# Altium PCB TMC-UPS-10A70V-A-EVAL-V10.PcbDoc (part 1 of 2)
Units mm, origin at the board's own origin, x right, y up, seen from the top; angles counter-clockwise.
Board outline 85 x 55 mm, 4 copper layers (Top Layer, Mid1, Mid2, Bottom Layer), stack 1.572 mm thick; 131 components, 65 nets, 443 pads, 731 vias.
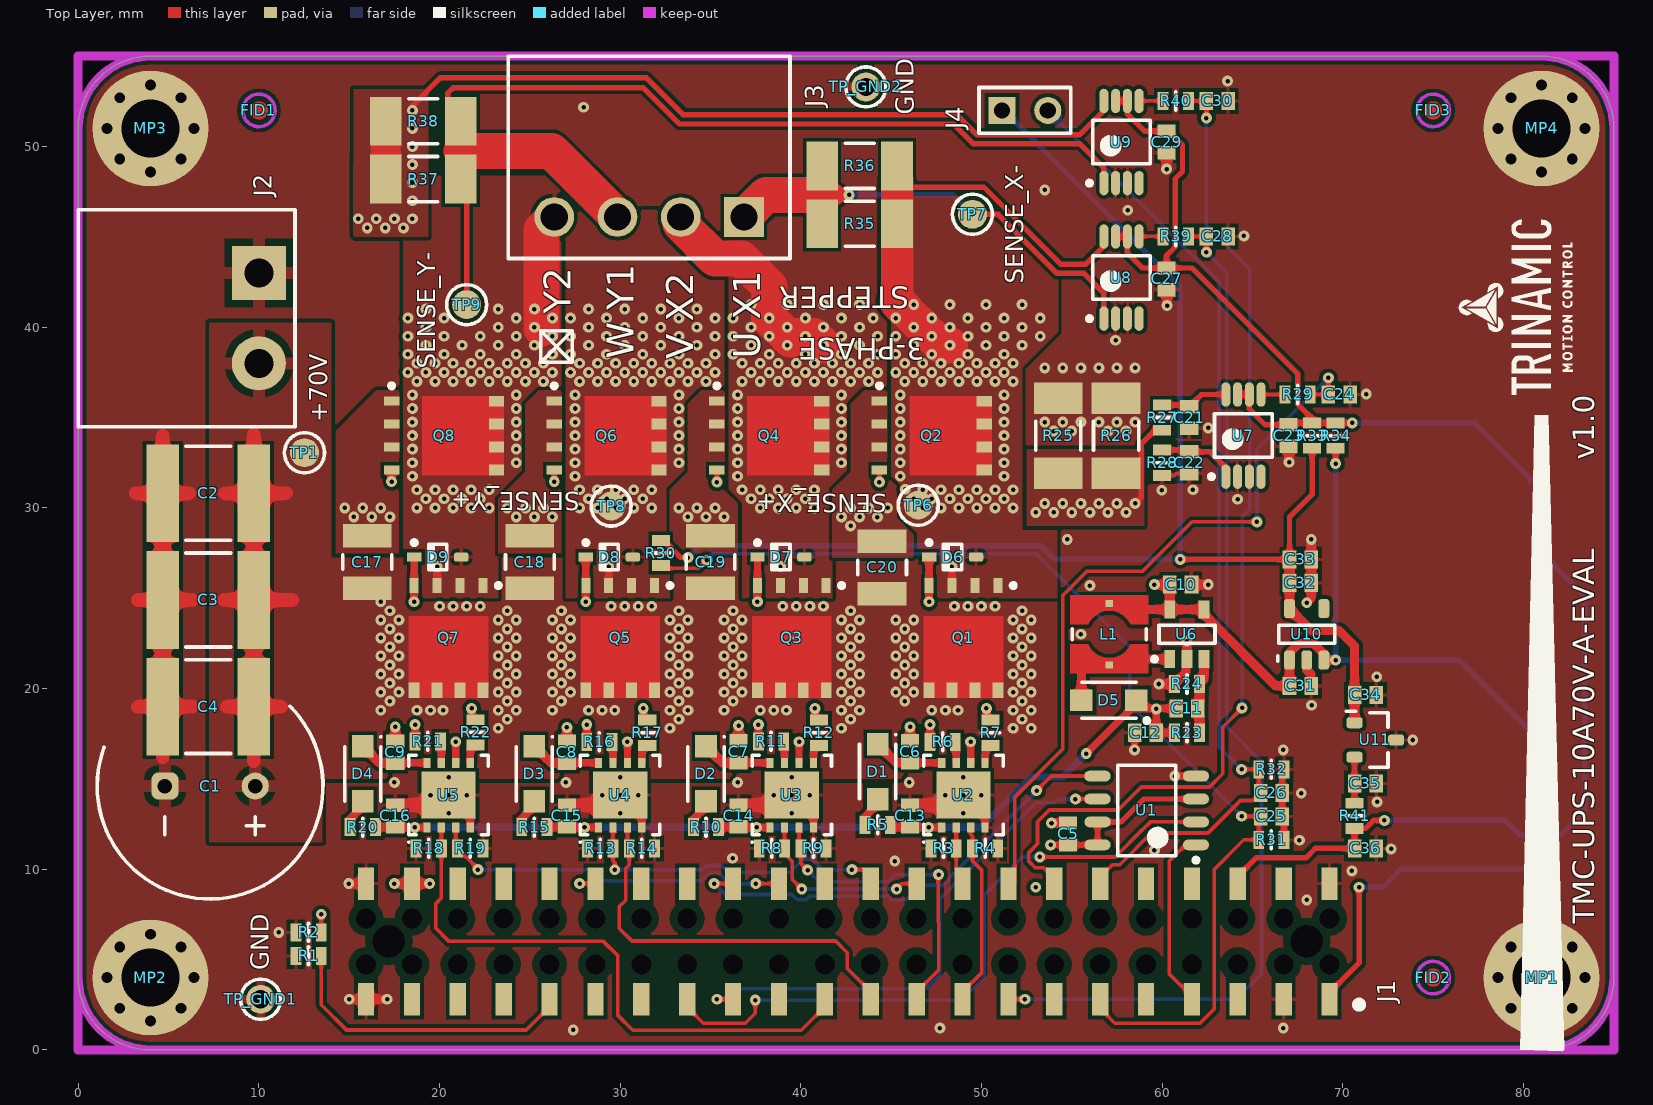
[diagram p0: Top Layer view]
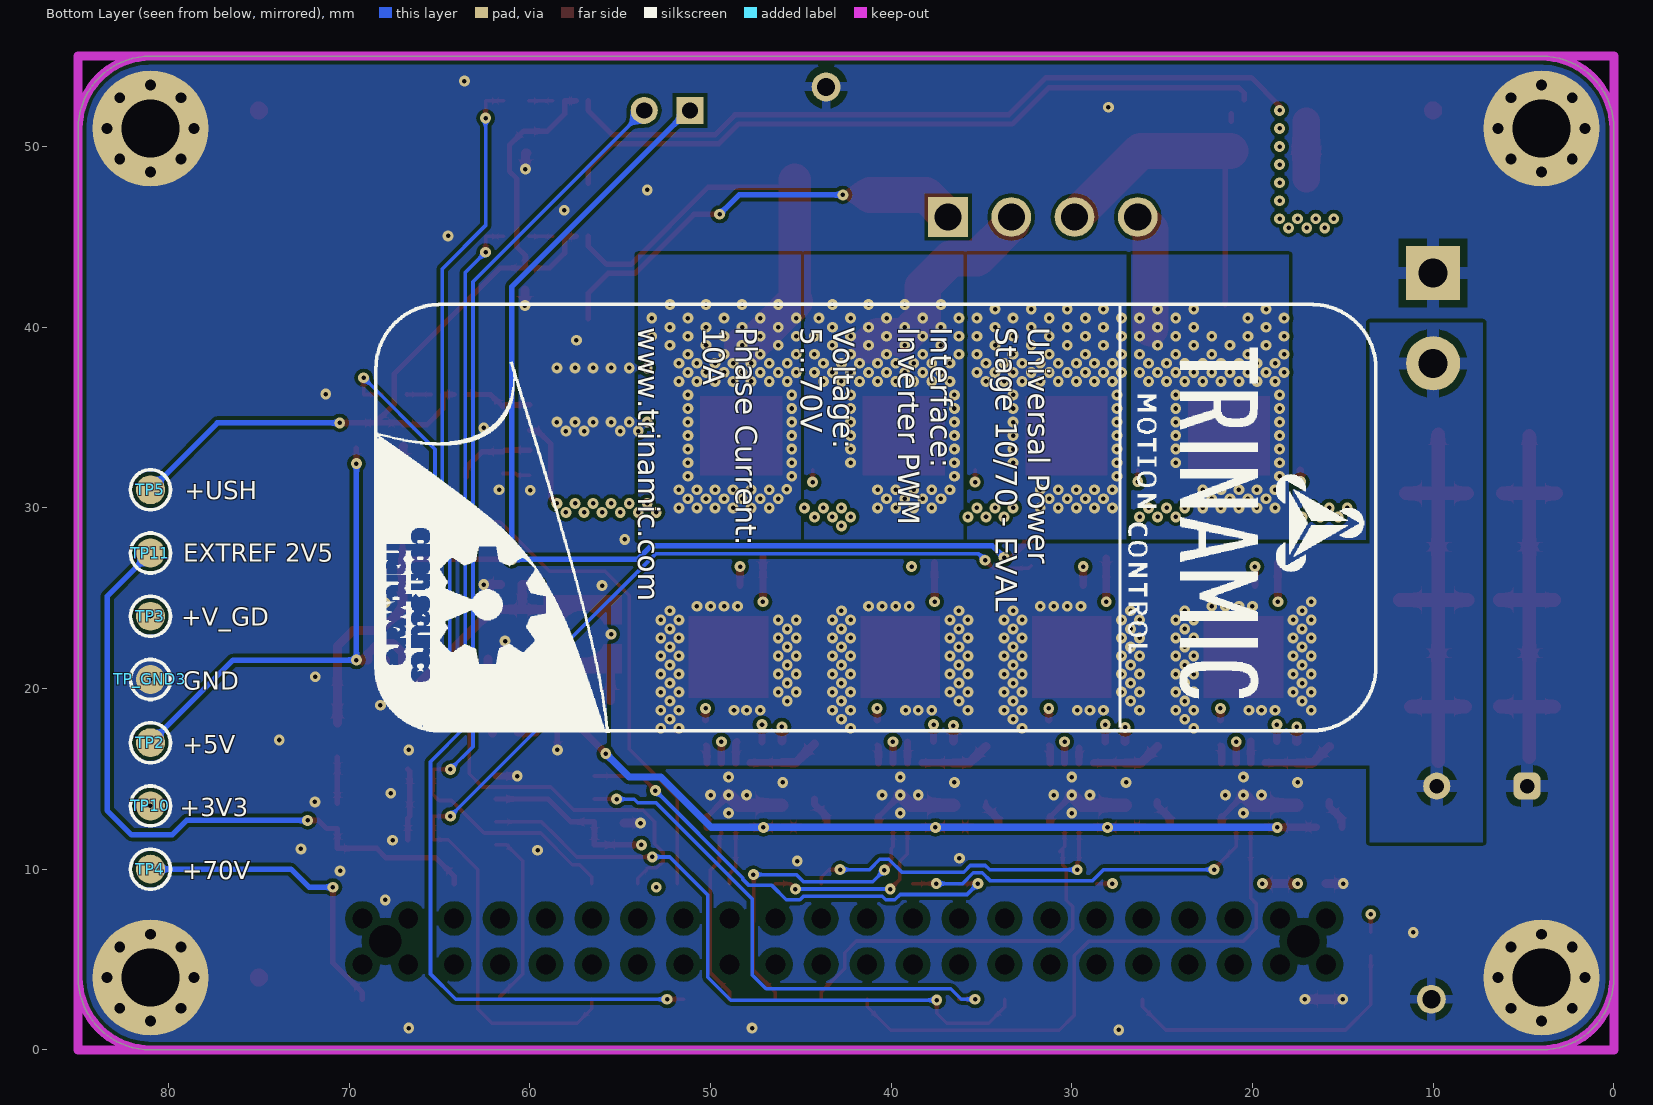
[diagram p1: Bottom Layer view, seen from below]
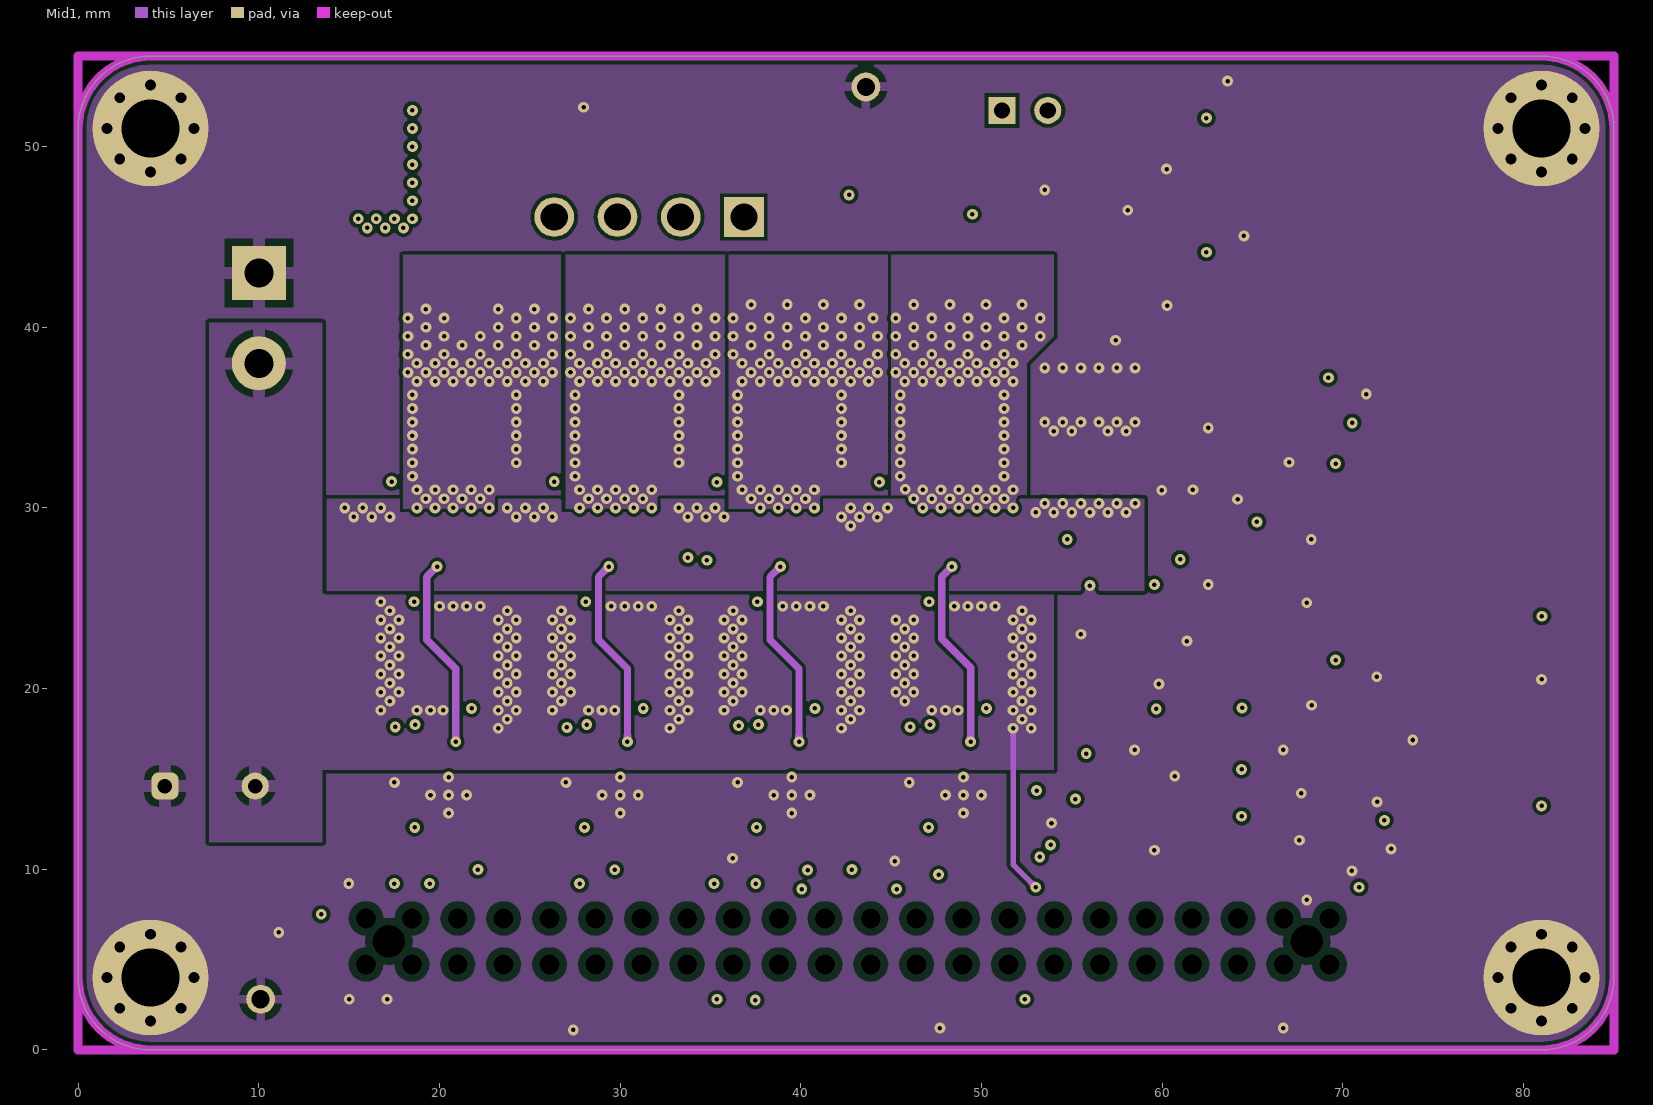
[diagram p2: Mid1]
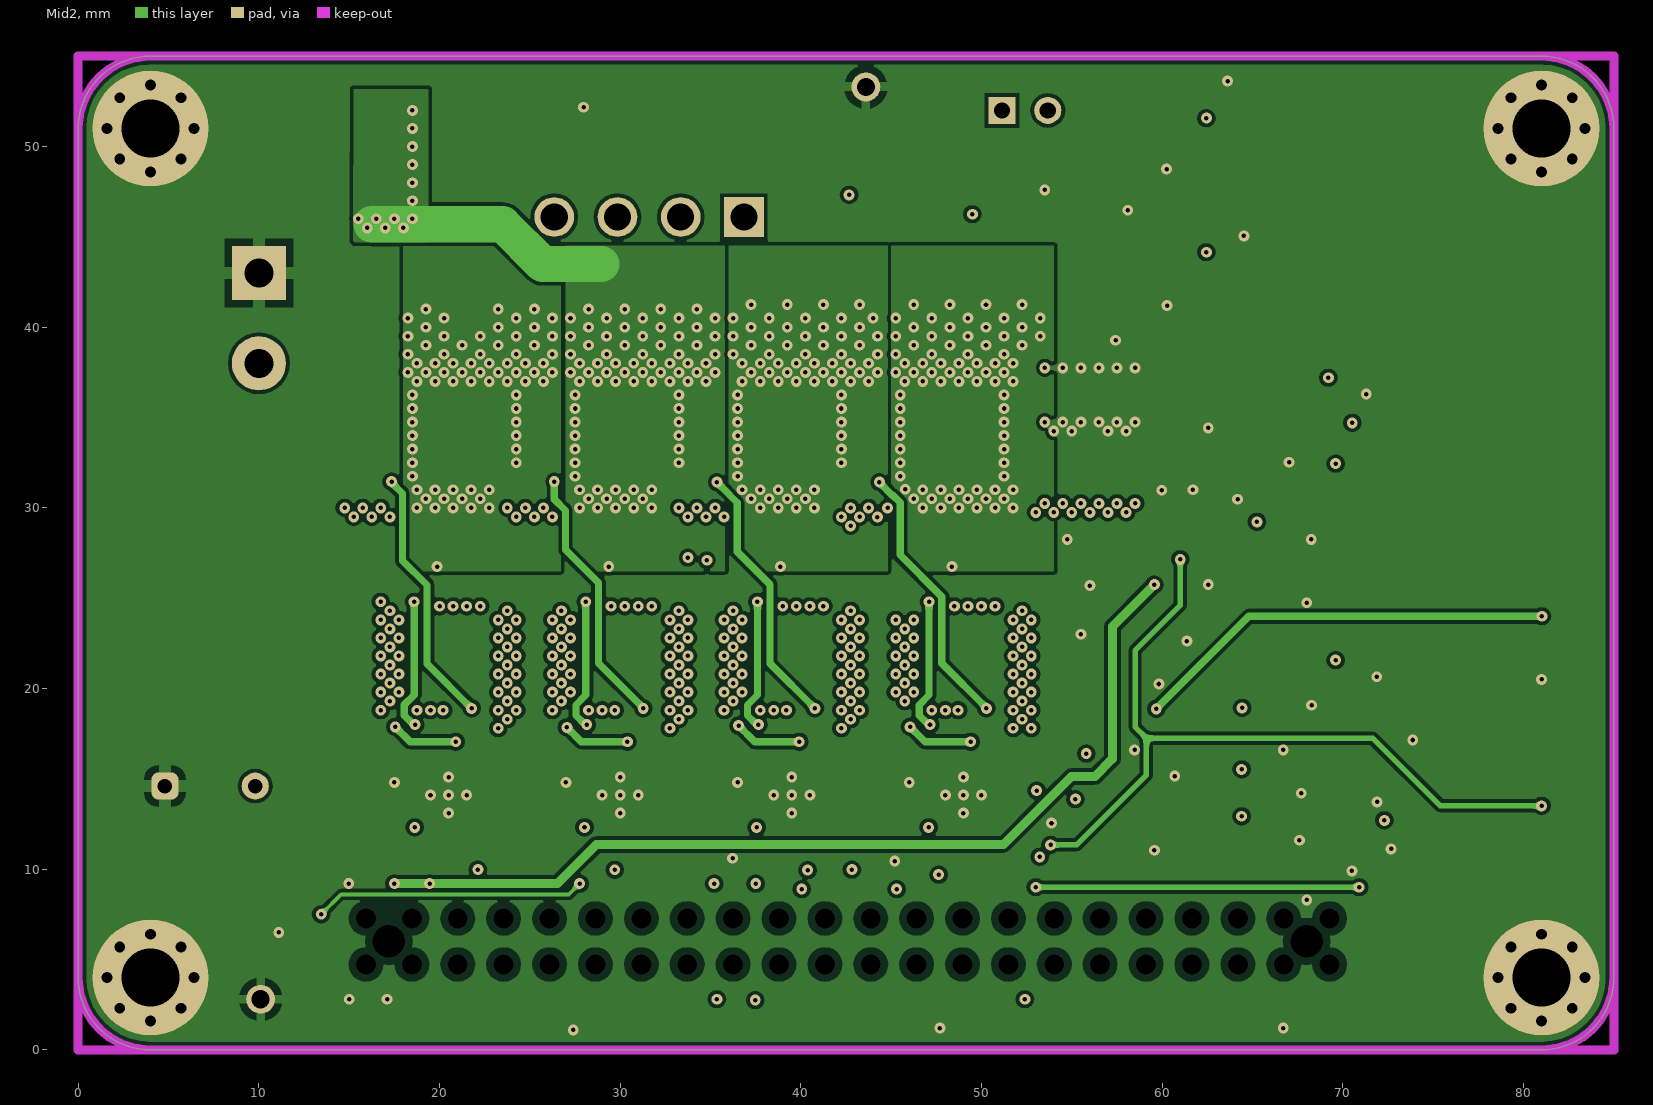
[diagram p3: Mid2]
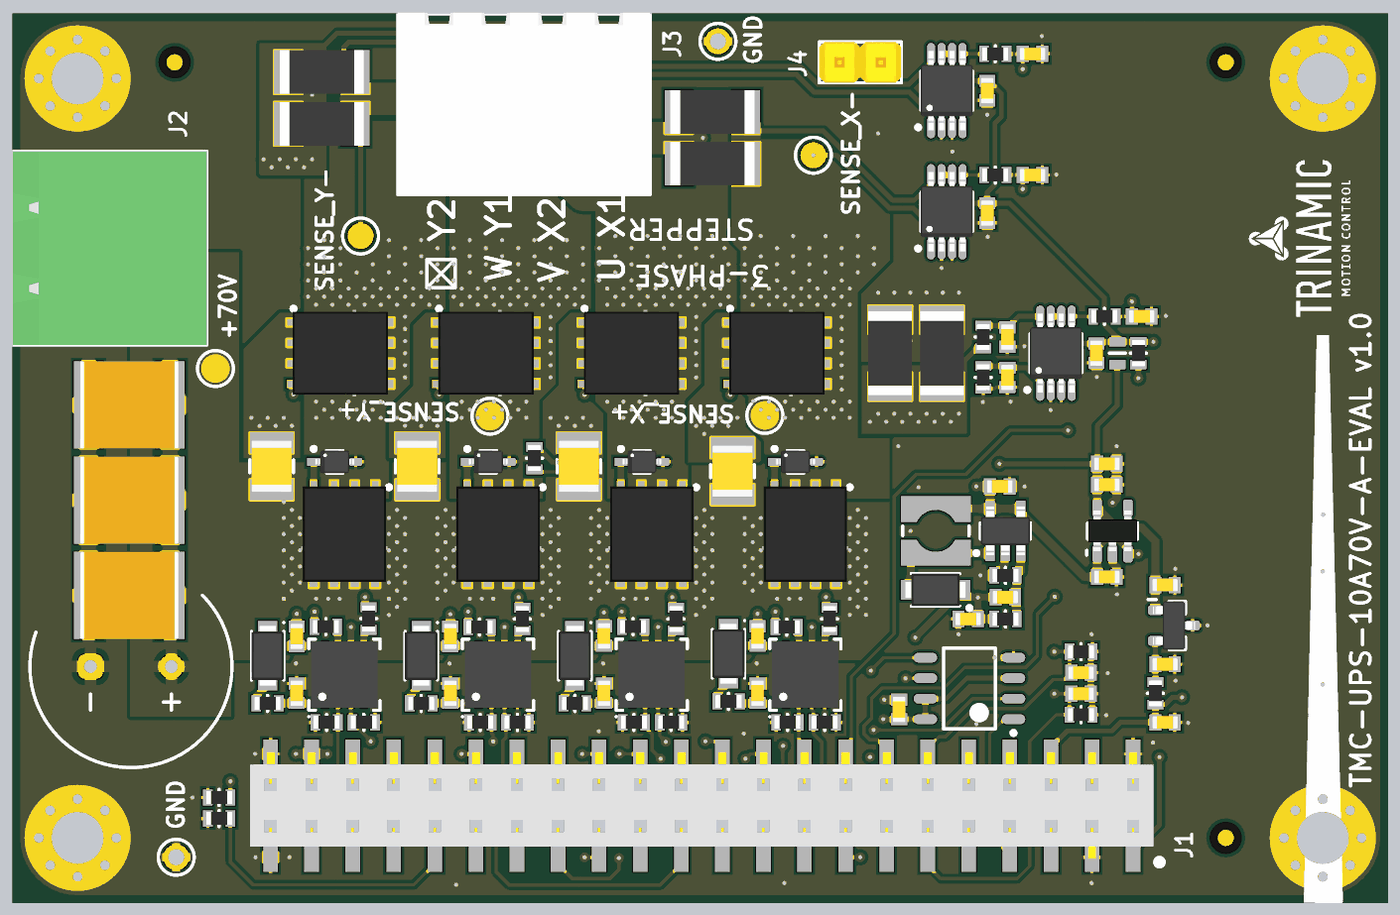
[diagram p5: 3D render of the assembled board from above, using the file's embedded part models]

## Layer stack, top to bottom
Top Soldermask: solder mask 0.0102, Solder Resist, Dk 3.5
Top Layer: signal copper 0.035
Prepreg 7628-45: prepreg 0.36, Dk 4.6
Mid1: signal copper 0.036
High Tg 1,08mm 35??m/35??m: core 0.71, FR-4, Dk 4.6
Mid2: signal copper 0.036
Prepreg 7628-45: prepreg 0.36, Dk 4.6
Bottom Layer: signal copper 0.035
Bottom Soldermask: solder mask 0.0102, Solder Resist, Dk 3.5

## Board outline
4,0 cw(c4,4) 0,4 0,51 cw(c4,51) 4,55 81,55 cw(c81,51) 85,51 85,4 cw(c81,4) 81,0

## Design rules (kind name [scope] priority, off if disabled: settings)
Clearance Clearance-unplated [IsPad and not PadIsPlated vs IsElectrical] p1: gap=0.4 ignorepadtopadclearanceinfootprint=FALSE
Clearance Clearance- [All] p2: gap=0.2 ignorepadtopadclearanceinfootprint=FALSE except(0: Arc-Hole Track-Hole SMDPad-Hole THPad-Hole Via-Hole Fill-Hole Poly-Hole Region-Hole Text-Hole; 0.125: SMDPad-SMDPad; 0.15: Track-SMDPad)
ComponentClearance [All] p1: gap=0 collisioncheckmode=3 verticalgap=0 showdistances=TRUE
DiffPairsRouting [All] p1: maxlimit=0.25 minlimit=0.25 mostfreqgap=0.25 toplayer_minwidth=0.381 toplayer_maxwidth=0.381 toplayer_prefwidth=0.381 midlayer1_minwidth=0.381 midlayer1_maxwidth=0.381 midlayer1_prefwidth=0.381 midlayer2_minwidth=0.381 midlayer2_maxwidth=0.381 midlayer2_prefwidth=0.381 bottomlayer_minwidth=0.381 bottomlayer_maxwidth=0.381 bottomlayer_prefwidth=0.381 maxuncoupledlength=12.5
FabricationTestpoint [All] p1: side=3 testpointundercomponent=TRUE minsize=0.5 maxsize=2.54 preferedsize=1.524 minholesize=0 maxholesize=1.016 preferedholesize=0.813 testpointgrid=0.025 allowsidetop=TRUE allowsidebottom=TRUE usegrid=FALSE gridtolerance=0
Height [All] p1: minheight=0 maxheight=40 prefheight=12.5
HoleSize HoleSize-PTH [All] p1: absolutevalues=TRUE maxlimit=6 minlimit=0.2 maxpercent=80.000 minpercent=20.000
HoleToHoleClearance [All] p1: gap=0.15 allowstackedmicrovias=TRUE
MinimumAnnularRing "Minimum IAR  >0.45mm" [((ObjectKind = 'Pad') OR (ObjectKind = 'Via')) And (Layer = 'MultiLayer') And (HoleDiameter > AsMM(0.45))] p1: minimumring=0.15 // minimum inner annular ring for pads > 0.45mm finished hole size
MinimumAnnularRing "Minimum IAR <=0.45mm" [((ObjectKind = 'Pad') OR (ObjectKind = 'Via')) And (Layer = 'MultiLayer') And (HoleDiameter <= AsMM(0.45))] p2: minimumring=0.15 // minimum inner annular ring for pads <= 0.45mm finished hole size
MinimumSolderMaskSliver [All] p1: minsoldermaskwidth=0.1
PlaneClearance PlaneClearance-IPI [All] p1: clearance=0.4
PlaneConnect [All] p1: planeconnectstyle=Relief reliefexpansion=0.4 reliefentries=4 reliefconductorwidth=0.2 reliefairgap=0.2
PolygonConnect PolygonConnect-Shunt [HasFootprint('RESC5025X07N')] p1: connectstyle=Direct reliefconductorwidth=0.254 reliefentries=4 polygonreliefangle="90 Angle" airgapwidth=0.254
PolygonConnect PolygonConnect-MT [HasFootprint('MTG3,2_6,4-VIA')] p2: connectstyle=Direct reliefconductorwidth=0.254 reliefentries=4 polygonreliefangle="90 Angle" airgapwidth=0.254
PolygonConnect PolygonConnect-JP2 [HasFootprint('691313710002')] p3: connectstyle=Relief reliefconductorwidth=0.7 reliefentries=4 polygonreliefangle="90 Angle" airgapwidth=0.4
PolygonConnect PolygonConnect-J1 [HasFootprint('AKL320-02')] p4: connectstyle=Relief reliefconductorwidth=0.7 reliefentries=4 polygonreliefangle="90 Angle" airgapwidth=0.4
PolygonConnect PolygonConnect-CAP [HasFootprint('CAPAE12_5X20')] p5: connectstyle=Relief reliefconductorwidth=0.7 reliefentries=4 polygonreliefangle="90 Angle" airgapwidth=0.4
PolygonConnect PolygonConnect-TP [HasFootprint('TP100P254')] p6: connectstyle=Direct reliefconductorwidth=0.254 reliefentries=4 polygonreliefangle="90 Angle" airgapwidth=0.254
PolygonConnect PolygonConnect-TP_1 [HasFootprint('TP100P254-TH')] p7: connectstyle=Relief reliefconductorwidth=0.5 reliefentries=4 polygonreliefangle="90 Angle" airgapwidth=0.4
PolygonConnect PolygonConnect-MOSFET [HasFootprint('PG-TDSON-8')] p8: connectstyle=Direct reliefconductorwidth=0.254 reliefentries=4 polygonreliefangle="90 Angle" airgapwidth=0.254
PolygonConnect PolygonConnect-CAPC3225N [HasFootprint('CAPC3225N')] p9: connectstyle=Direct reliefconductorwidth=0.254 reliefentries=4 polygonreliefangle="90 Angle" airgapwidth=0.254
PolygonConnect PolygonConnect-Via [IsVia] p10: connectstyle=Direct reliefconductorwidth=0.2 reliefentries=4 polygonreliefangle="90 Angle" airgapwidth=0.254
PolygonConnect PolygonConnect-xTW [All] p11: connectstyle=Relief reliefconductorwidth=0.2 reliefentries=4 polygonreliefangle="90 Angle" airgapwidth=0.2
RoutingCorners [All] p1: cornerstyle=45-Degree minsetback=2.5 maxsetback=2.5
RoutingVias "RoutingVias <= 0.45mm" [All] p1: holewidth=0.25 width=0.6 viastyle="Through Hole" minholewidth=0.2 minwidth=0.5 maxholewidth=0.6 maxwidth=1
SilkToSilkClearance [All] p1: silktosilkclearance=0.2
SilkToSolderMaskClearance SilkscreenOverComponentPads [IsPad] p1: minsilkscreentomaskgap=0.2 clearancetoexposedcopper=TRUE
SolderMaskExpansion SolderMaskExpansionVia [IsVia] p1: expansion=0.1 soldermaskfromhole=TRUE
SolderMaskExpansion [All] p2: expansion=0.08
Width Width-xTW [All] p1: maxlimit=2 minlimit=0.15 preferedwidth=0.2 midlayer1_minwidth=0.2 midlayer2_minwidth=0.2 bottomlayer_minwidth=0.2 minimp=50.000000 maximp=50.000000 favimp=50.000000
18 further rules are at their usual default settings.

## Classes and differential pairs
component class TMC-UPS-10A70V-A-EVAL-V10_Power_Sense: C27 C28 C29 C30 C31 C32 C33 C34 C35 C36 R35 R36 R37 R38 R39 R40 R41 TP6 TP7 TP8 TP9 TP10 TP11 U8 U9 U10 U11
component class TMC-UPS-10A70V-A-EVAL-V10_MOSFETs: C17 C18 C19 C20 C21 C22 C23 C24 C25 C26 D6 D7 D8 D9 J4 Q1 Q2 Q3 Q4 Q5 Q6 Q7 Q8 R25 R26 R27 R28 R29 R30 R31 R32 R33 R34 TP4 TP5 U7
component class TMC-UPS-10A70V-A-EVAL-V10_Predriver: C6 C7 C8 C9 C10 C11 C12 C13 C14 C15 C16 D1 D2 D3 D4 D5 L1 R3 R4 R5 R6 R7 R8 R9 R10 R11 R12 R13 R14 R15 R16 R17 R18 R19 R20 R21 R22 R23 R24 TP2 TP3 U2 U3 U4 U5 U6
component class TMC-UPS-10A70V-A-EVAL-V10_Main: C1 C2 C3 C4 C5 J1 J2 J3 MP1 MP2 MP3 MP4 R1 R2 TP1 TP_GND1 TP_GND2 TP_GND3 U1

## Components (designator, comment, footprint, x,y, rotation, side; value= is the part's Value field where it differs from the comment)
C1 "CAPP2" CAPAE12_5X20 7.3,14.6 r0 top
C2 "CAPC" CAPC5750X28N 7.2,30.8 r0 top value=10u
C3 "CAPC" CAPC5750X28N 7.2,24.9 r0 top value=10u
C4 "CAPC" CAPC5750X28N 7.2,19 r0 top value=10u
C5 "CAPC" CAPC1608N 54.8,11.95 r270 top value=100n
C6 "" CAPC1608N 46.05,16.5 r90 top value=100n
C7 "" CAPC1608N 36.55,16.5 r90 top value=100n
C8 "" CAPC1608N 27.05,16.475 r90 top value=100n
C9 "" CAPC1608N 17.55,16.475 r90 top value=100n
C10 "CAPC" CAPC1608N 61.025,25.75 r180 top value=10u
C11 "CAPC" CAPC1608N 61.375,18.9 r180 top value=25p
C12 "CAPC" CAPC1608N 59.075,17.55 r0 top value=4.7u
C13 "CAPC" CAPC1608N 46.05,12.95 r270 top value=1u
C14 "CAPC" CAPC1608N 36.55,12.95 r270 top value=1u
C15 "CAPC" CAPC1608N 27.05,12.95 r270 top value=1u
C16 "CAPC" CAPC1608N 17.55,12.95 r270 top value=1u
C17 "CAPC" CAPC3225N 16,27 r270 top value=4.7u
C18 "CAPC" CAPC3225N 25,27 r270 top value=4.7u
C19 "CAPC" CAPC3225N 35,27 r270 top value=4.7u
C20 "CAPC" CAPC3225N 44.5,26.7 r270 top value=4.7u
C21 "CAPC" CAPC1608N 61.5,35 r90 top value=100p
C22 "CAPC" CAPC1608N 61.5,32.5 r90 top value=100p
C23 "CAPC" CAPC1608N 67,34 r90 top value=100n
C24 "" CAPC1608N 69.8,36.275 r180 top value=2.2n
C25 "CAPC" CAPC1608N 66.05,12.925 r180 top value=100n
C26 "CAPC" CAPC1608N 66.05,14.225 r180 top value=100n
C27 "CAPC" CAPC1608N 60.25,42.675 r270 top value=100n
C28 "" CAPC1608N 63.05,45.025 r180 top value=2.2n
C29 "CAPC" CAPC1608N 60.25,50.25 r90 top value=100n
C30 "" CAPC1608N 63.05,52.525 r180 top value=2.2n
C31 "CAPC" CAPC1608N 67.65,20.15 r180 top value=100n
C32 "CAPC" CAPC1608N 67.65,25.85 r180 top value=4.7u
C33 "CAPC" CAPC1608N 67.65,27.15 r180 top value=100n
C34 "CAPC" CAPC1608N 71.25,19.65 r180 top value=100n
C35 "CAPC" CAPC1608N 71.25,14.75 r180 top value=100n
C36 "CAPC" CAPC1608N 71.25,11.15 r180 top value=100n
D1 "DIO-SCHOTTKY" SODFL370X140-2N 44.25,15.4 r270 top value="1A, 100V"
D2 "DIO-SCHOTTKY" SODFL370X140-2N 34.75,15.275 r270 top value="1A, 100V"
D3 "DIO-SCHOTTKY" SODFL370X140-2N 25.25,15.275 r270 top value="1A, 100V"
D4 "DIO-SCHOTTKY" SODFL370X140-2N 15.75,15.275 r270 top value="1A, 100V"
D5 "DIO-SCHOTTKY" SODFL370X140-2N 57.05,19.35 r180 top value="1A, 100V"
D6 "ZENER" SOD2512X100N 48.4,27.275 r0 top value="13V, 0.3W"
D7 "ZENER" SOD2512X100N 38.9,27.275 r0 top value="13V, 0.3W"
D8 "ZENER" SOD2512X100N 29.4,27.275 r0 top value="13V, 0.3W"
D9 "ZENER" SOD2512X100N 19.9,27.275 r0 top value="13V, 0.3W"
FID1 "Comment" FID10X20 10,52 r90 top
FID2 "Comment" FID10X20 75,4 r90 top
FID3 "Comment" FID10X20 75,52 r90 top
J1 "PTC" HLE-122-02-F-DV 42.6,6 r180 top locked value=44pin
J2 "HDR1x2A" AKL320-02 10,40.5 r90 top locked value="2 pin"
J3 "HDR1x4A" PT11304HBBN 31.6,46.1 r0 top locked value="4 pin, 3.5mm"
J4 "HDR1x2" HDRP1X2_2_54 52.4,52 r0 top locked value="2 pin"
L1 "INDM" 744031100 57.075,23 r270 top value=10u
MP1 "MTG" MTG3,2_6,4-VIA 81,4 r90 top value="3.2x6.4 VIA"
MP2 "MTG" MTG3,2_6,4-VIA 4,4 r90 top value="3.2x6.4 VIA"
MP3 "MTG" MTG3,2_6,4-VIA 4,51 r90 top value="3.2x6.4 VIA"
MP4 "MTG" MTG3,2_6,4-VIA 81,51 r90 top value="3.2x6.4 VIA"
Q1 "" PG-TDSON-8 49,22.8 r180 top value="80V 100A"
Q2 "" PG-TDSON-8 47.25,34 r270 top value="80V 100A"
Q3 "" PG-TDSON-8 39.5,22.8 r180 top value="80V 100A"
Q4 "" PG-TDSON-8 38.25,34 r270 top value="80V 100A"
Q5 "" PG-TDSON-8 30,22.8 r180 top value="80V 100A"
Q6 "" PG-TDSON-8 29.25,34 r270 top value="80V 100A"
Q7 "" PG-TDSON-8 20.5,22.8 r180 top value="80V 100A"
Q8 "" PG-TDSON-8 20.25,34 r270 top value="80V 100A"
R1 "RESC" RESC1608N 12.75,5.2 r0 top value=10k
R2 "RESC" RESC1608N 12.75,6.5 r0 top value=10k
R3 "RESC" RESC1608N 47.9,11.15 r0 top value=10k
R4 "RESC" RESC1608N 50.2,11.15 r180 top value=10k
R5 "" RESC1608N 44.25,12.45 r180 top value=2.2
R6 "" RESC1608N 47.85,17.05 r180 top value=2.2
R7 "" RESC1608N 50.5,17.55 r90 top value=2.2
R8 "RESC" RESC1608N 38.4,11.15 r0 top value=10k
R9 "RESC" RESC1608N 40.7,11.15 r180 top value=10k
R10 "" RESC1608N 34.75,12.325 r180 top value=2.2
R11 "" RESC1608N 38.35,17.075 r180 top value=2.2
R12 "" RESC1608N 41,17.55 r90 top value=2.2
R13 "RESC" RESC1608N 28.9,11.15 r0 top value=10k
R14 "RESC" RESC1608N 31.2,11.15 r180 top value=10k
R15 "" RESC1608N 25.25,12.325 r180 top value=2.2
R16 "" RESC1608N 28.85,17.05 r180 top value=2.2
R17 "" RESC1608N 31.5,17.55 r90 top value=2.2
R18 "RESC" RESC1608N 19.4,11.15 r0 top value=10k
R19 "RESC" RESC1608N 21.7,11.15 r180 top value=10k
R20 "" RESC1608N 15.75,12.325 r180 top value=2.2
R21 "" RESC1608N 19.35,17.075 r180 top value=2.2
R22 "" RESC1608N 22,17.575 r90 top value=2.2
R23 "RESC" RESC1608N 61.375,17.55 r180 top value=12k
R24 "RESC" RESC1608N 61.375,20.25 r0 top value=1.5k
R25 "RESC" RESC5025X07N 54.25,34 r270 top value=15m
R26 "RESC" RESC5025X07N 57.45,34 r270 top value=15m
R27 "RESC" RESC1608N 60,35 r90 top value=100
R28 "RESC" RESC1608N 60,32.5 r90 top value=100
R29 "RESC" RESC1608N 67.5,36.275 r0 top value=1k
R30 "RESC" RESC1608N 32.25,27.5 r90 top value="10k NTC"
R31 "RESC" RESC1608N 66.05,11.625 r180 top value=10k
R32 "RESC" RESC1608N 66.05,15.525 r180 top value=10k
R33 "RESC" RESC1608N 68.3,34 r90 top value=DNP
R34 "RESC" RESC1608N 69.6,34 r90 top value=0
R35 "RESC" RESC5025X07N 43.25,45.725 r0 top value=15m
R36 "RESC" RESC5025X07N 43.25,48.925 r0 top value=15m
R37 "RESC" RESC5025X07N 19.1,48.2 r180 top value=15m
R38 "RESC" RESC5025X07N 19.1,51.4 r180 top value=15m
R39 "RESC" RESC1608N 60.75,45.025 r0 top value=1k
R40 "RESC" RESC1608N 60.75,52.525 r0 top value=1k
R41 "RESC" RESC1608N 70.65,12.95 r270 top value=10
TP1 "+70V" TP100P254 12.525,33.05 r0 top value="c160 (P100 probe)"
TP2 "+5V" TP100P254 81,17 r180 bottom value="c160 (P100 probe)"
TP3 "+V_GD" TP100P254 81,24 r180 bottom value="c160 (P100 probe)"
TP4 "+70V" TP100P254 81,10 r180 bottom value="c160 (P100 probe)"
TP5 "+USH" TP100P254 81,31 r180 bottom value="c160 (P100 probe)"
TP6 "SENSE_X+" TP100P254 46.5,30.15 r90 top locked value="c160 (P100 probe)"
TP7 "SENSE_X-" TP100P254 49.5,46.25 r90 top locked value="c160 (P100 probe)"
TP8 "SENSE_Y+" TP100P254 29.5,30.1 r90 top locked value="c160 (P100 probe)"
TP9 "SENSE_Y-" TP100P254 21.5,41.25 r90 top value="c160 (P100 probe)"
TP10 "+3V3" TP100P254 81,13.5 r180 bottom value="c160 (P100 probe)"
TP11 "EXTREF 2V5" TP100P254 81,27.5 r180 bottom value="c160 (P100 probe)"
TP_GND1 "GND" TP100P254-TH 10.1,2.8 r180 top locked value="c160h100 (P100 TH)"
TP_GND2 "GND" TP100P254-TH 43.6,53.3 r180 top locked value="c160h100 (P100 TH)"
TP_GND3 "GND" TP100P254 81,20.5 r180 bottom value="c160 (P100 probe)"
U1 "" SOIC127P600X175-8N 59.15,13.25 r180 top value=128Kb
U2 "" PSON80P400X80_HS-9N 49,14.1 r90 top value="108V 1A"
U3 "" PSON80P400X80_HS-9N 39.5,14.1 r90 top value="108V 1A"
U4 "" PSON80P400X80_HS-9N 30,14.1 r90 top value="108V 1A"
U5 "" PSON80P400X80_HS-9N 20.5,14.1 r90 top value="108V 1A"
U6 "LMR62014" SOT95P280X145-5N 61.375,23 r90 top value=1.4A
U7 "*" TSOP65P490X95-8N 64.5,34 r90 top value=CMVR{}70V
U8 "*" TSOP65P490X95-8N 57.75,42.75 r90 top value=CMVR{}70V
U9 "*" TSOP65P490X95-8N 57.75,50.25 r90 top value=CMVR{}70V
U10 "" SOT95P270X145-5N 68,23 r90 top value="150mA 3.3V"
U11 "*" SOT95P280X130-3N 71.8,17.15 r0 top value=2.5V

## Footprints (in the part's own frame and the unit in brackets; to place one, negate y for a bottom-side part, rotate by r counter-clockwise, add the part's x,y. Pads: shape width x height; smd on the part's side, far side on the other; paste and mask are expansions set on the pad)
744031100 [mm] "Wuerth Precision Wire Wound Inductor, 2-Leads, Body 3.80x3.80mm, IPC Medium Density"
  rect 0.4x0.4 smd: 1(-1.7,0) 2(1.7,0)
  Top Layer region: 0.55,2.15 2.15,2.15 2.15,-2.15 0.55,-2.15 0.55,-1.179 0.549,-1.179 1.01,-0.819 1.267,-0.293 1.267,0.293 1.01,0.819 0.549,1.179 0.549,1.179 0.55,1.182
  Top Layer region: -0.55,-2.15 -2.15,-2.15 -2.15,2.15 -0.55,2.15 -0.55,1.179 -0.549,1.179 -1.01,0.819 -1.267,0.293 -1.267,-0.293 -1.01,-0.819 -0.549,-1.179 -0.549,-1.179 -0.55,-1.182
  silkscreen extent -0.3,-2.05 0.3,2.05, body extent -2.05,-2.05 2.05,2.05, height 1.8
AKL320-02 [mm] "Box header for AKL 349, 2-pin, RM 5.0"
  rect 3x3 hole 1.6: 1(2.5,0)
  round 3 hole 1.6: 2(-2.5,0)
  silkscreen extent -6,-2 6,10, body extent -6,-2 6,10, height 8.55
CAPAE12_5X20 [mm] "Aluminium Capacitor, Radial, H=20mm, D=12.5mm"
  rrect50% 1.5x1.5 hole 0.8: 1(-2.5,0)
  round 1.5 hole 0.8: 2(2.5,0)
  silkscreen extent -6.25,-6.25 6.25,4.42
CAPC1608N [mm] "Chip capacitor. C1608 (0603)."
  rect 0.75x1 smd: 1(-0.6,0) 2(0.6,0)
  body extent -0.8,-0.4 0.8,0.4, height 0.92
CAPC3225N [mm] "Chip capacitor. C3225 (1210)."
  rect 1.3x2.7 smd: 1(-1.45,0) 2(1.45,0)
  silkscreen extent -0.4,-1.35 0.4,1.35, body extent -1.6,-1.25 1.6,1.25, height 2.79
CAPC5750X28N [mm] "Chip Capacitor, 2-Leads, Body 5.70x5.00mm, IPC Medium Density"
  rect 1.8x5.4 smd: 1(-2.525,0) 2(2.525,0)
  silkscreen extent -1.25,-2.6 1.25,2.6, body extent -3.05,-2.7 3.05,2.7, height 2.79
FID10X20 [mm] "Fiducial"
  Top Layer circle w0.5: c0,0 r0.25
  Top Layer keep-out circle w0.2: c0,0 r0.9
HDRP1X2_2_54 [mm] "Pin Header, Single Row, 2 pos, 2.54mm"
  rect 1.5x1.5 hole 0.9: 1(-1.27,0)
  round 1.5 hole 0.9: 2(1.27,0)
  silkscreen extent -2.54,-1.27 2.54,1.27, body extent -2.54,-1.27 2.54,1.27, height 9.5
HLE-122-02-F-DV [mm] "24 Position Receptacle, Bottom Entry Connector Gold 0.100\" (2.54mm) Surface Mount"
  round 1 hole 1.1 unplated: 0(-26.67,-1.27) 0(-26.67,1.27) 0(-24.13,-1.27) 0(-24.13,1.27) 0(-21.59,-1.27) 0(-21.59,1.27) 0(-19.05,-1.27) 0(-19.05,1.27) 0(-16.51,-1.27) 0(-16.51,1.27) 0(-13.97,-1.27) 0(-13.97,1.27) 0(-11.43,-1.27) 0(-11.43,1.27) 0(-8.89,-1.27) 0(-8.89,1.27) 0(-6.35,-1.27) 0(-6.35,1.27) 0(-3.81,-1.27) 0(-3.81,1.27) 0(-1.27,1.27) 0(-1.27,-1.27) 0(1.27,1.27) 0(1.27,-1.27) 0(3.81,-1.27) 0(3.81,1.27) 0(6.35,-1.27) 0(6.35,1.27) 0(8.89,-1.27) 0(8.89,1.27) 0(11.43,-1.27) 0(11.43,1.27) 0(13.97,-1.27) 0(13.97,1.27) 0(16.51,-1.27) 0(16.51,1.27) 0(19.05,-1.27) 0(19.05,1.27) 0(21.59,-1.27) 0(21.59,1.27) 0(24.13,-1.27) 0(24.13,1.27) 0(26.67,-1.27) 0(26.67,1.27)
  round 1 hole 1.8 unplated: 0(-25.4,0) 0(25.4,0)
  rect 0.9x1.8 smd: 1(-26.67,3.2) 2(-26.67,-3.2) 3(-24.13,3.2) 4(-24.13,-3.2) 5(-21.59,3.2) 6(-21.59,-3.2) 7(-19.05,3.2) 8(-19.05,-3.2) 9(-16.51,3.2) 10(-16.51,-3.2) 11(-13.97,3.2) 12(-13.97,-3.2) 13(-11.43,3.2) 14(-11.43,-3.2) 15(-8.89,3.2) 16(-8.89,-3.2) 17(-6.35,3.2) 18(-6.35,-3.2) 19(-3.81,3.2) 20(-3.81,-3.2) 21(-1.27,3.2) 22(-1.27,-3.2) 23(1.27,3.2) 24(1.27,-3.2) 25(3.81,3.2) 26(3.81,-3.2) 27(6.35,3.2) 28(6.35,-3.2) 29(8.89,3.2) 30(8.89,-3.2) 31(11.43,3.2) 32(11.43,-3.2) 33(13.97,3.2) 34(13.97,-3.2) 35(16.51,3.2) 36(16.51,-3.2) 37(19.05,3.2) 38(19.05,-3.2) 39(21.59,3.2) 40(21.59,-3.2) 41(24.13,3.2) 42(24.13,-3.2) 43(26.67,3.2) 44(26.67,-3.2)
  silkscreen extent -28.5,3.3 -28.1,3.7, body extent -27.94,-3.29 27.94,3.29, height 3.51
MTG3,2_6,4-VIA [mm] "3,2mm ID/6.4mm OD mounting hole, reinforced with vias"
  round 6.4 hole 3.2 paste-3.3: 1(0,0)
PG-TDSON-8 [mm]
  rect 0.5x0.85 smd paste-0.05: 1(-1.905,-2.9) 2(-0.635,-2.9) 3(0.635,-2.9) 4(1.905,-2.9)
  rect 0.6x0.85 smd paste-0.05: 5(1.905,2.9) 6(0.635,2.9) 7(-0.635,2.9) 8(-1.905,2.9)
  rect 0.1x0.1 smd paste-1 mask-1: 9(-0.1,0)
  Top Layer region: -2.205,-1.225 2.205,-1.225 2.205,3.325 -2.205,3.325
  silkscreen extent -2.88,-3.02 -2.63,-2.78, body extent -2.68,-3.08 2.67,3.07, height 1
PSON80P400X80_HS-9N [mm] "PSON, 8-Leads, Body 4.00x4.00mm, Pitch 0.80mm, Thermal Pad 3.00x2.60mm, IPC Medium Density"
  rect 0.55x0.4 smd: 1(-1.785,1.2) 2(-1.785,0.4) 3(-1.785,-0.4) 4(-1.785,-1.2) 5(1.785,-1.2) 6(1.785,-0.4) 7(1.785,0.4) 8(1.785,1.2)
  rect 2.6x3 smd paste-1.3: 9(0,0)
  silkscreen extent -2.65,-2.2 2.2,2.25, body extent -2.05,-2.05 2.05,2.05, height 0.8
PT11304HBBN [mm] "3.50 mm centerline, PT113xxHBBN Typ 182, pin header"
  rect 2.2x2.2 hole 1.5: 1(5.25,0)
  round 2.2 hole 1.5: 2(1.75,0) 3(-1.75,0) 4(-5.25,0)
  silkscreen extent -7.8,-2.3 7.8,8.9, body extent -7.8,-2.2 7.8,9, height 8.7
RESC1608N [mm] "Chip resistor C1608 (0603)."
  rect 0.6x1 smd: 1(-0.7,0) 2(0.7,0)
  silkscreen extent 0,-0.5 0,0.5, body extent -0.8,-0.4 0.8,0.4, height 0.45
RESC5025X07N [mm] "Chip Resistor, 2-Leads, Body 5.00x2.50mm, IPC Medium Density"
  rect 1.75x2.7 smd: 1(-2.075,0) 2(2.075,0)
  silkscreen extent -0.8,-1.25 0.8,1.25, body extent -2.6,-1.35 2.6,1.35, height 0.7
SOD2512X100N [mm] "SOD323 (SC-76), 2-Leads, Body 1.25x1.70mm, IPC Medium Density"
  rect 0.8x0.5 smd: 1(-1.3,0)
  rrect50% 0.8x0.5 smd: 2(1.3,0)
  silkscreen extent -1.42,-0.7 0.5,0.92, body extent -1.24,-0.7 1.24,0.7, height 1.1
SODFL370X140-2N [mm] "SODFL, 2-Leads, Body 1.80x3.70mm, IPC Medium Density"
  rect 1.25x1.2 smd: 1(-1.525,0) 2(1.525,0)
  silkscreen extent -2.1,-1 1.5,1.05, body extent -1.85,-1 1.85,1, height 1.4
SOIC127P600X175-8N [mm] "SOIC, 8-Leads, Body 4.90x3.90mm, Pitch 1.27mm, IPC Medium Density"
  oval 1.45x0.6 smd: 1(-2.725,1.905) 2(-2.725,0.635) 3(-2.725,-0.635) 4(-2.725,-1.905) 5(2.725,-1.905) 6(2.725,-0.635) 7(2.725,0.635) 8(2.725,1.905)
  silkscreen extent -2.85,-2.5 1.6,2.88, body extent -2,-2.5 2,2.5, height 1.75
SOT95P270X145-5N [mm] "SOT23, 5-Leads, Body 2.90x2.70mm, Pitch 0.95mm, IPC Medium Density"
  rrect50% 1.05x0.6 smd: 1(-1.425,0.95) 2(-1.425,0) 3(-1.425,-0.95) 4(1.425,-0.95) 5(1.425,0.95)
  silkscreen extent -1.5,-1.55 0.5,1.6, body extent -1.25,-1.5 1.25,1.5, height 1.1
SOT95P280X130-3N [mm] "SOT23, 3-Leads, Body 2.95x2.80mm, Pitch 0.95mm, IPC Medium Density"
  rrect50% 0.9x0.6 smd: 1(-1.15,0.95) 2(-1.15,-0.95) 3(1.15,0)
  silkscreen extent -1.6,-1.5 0.7,1.6, body extent -1.3,-1.5 1.3,1.5, height 1.1
SOT95P280X145-5N [mm] "SOT23, 5-Leads, Body 2.90x2.80mm, Pitch 0.95mm, IPC Medium Density"
  rect 1x0.6 smd: 1(-1.375,0.95) 2(-1.375,0) 3(-1.375,-0.95) 4(1.375,-0.95) 5(1.375,0.95)
  silkscreen extent -1.5,-1.55 0.5,1.92, body extent -1.5,-1.53 1.5,1.53, height 1.45
TP100P254 [mm] "1mm testpoint for 2.54mm pitch"
  round 1.6 smd paste-1: 1(0,0)
  silkscreen extent -1.11,-1.11 1.11,1.11
TP100P254-TH [mm] "1mm TH loop test-point for 2.54+ mm pitch"
  round 1.6 hole 1 paste-1: 1(0,0)
  silkscreen extent -1.11,-1.11 1.11,1.11
TSOP65P490X95-8N [mm] "TSOP, 8-Leads, Body 3.00x3.00mm, Pitch 0.65mm, IPC Medium Density"
  oval 1.35x0.5 smd: 1(-2.275,0.975) 2(-2.275,0.325) 3(-2.275,-0.325) 4(-2.275,-0.975) 5(2.275,-0.975) 6(2.275,-0.325) 7(2.275,0.325) 8(2.275,0.975)
  silkscreen extent -2.4,-1.6 1.2,1.9, body extent -2.45,-1.6 2.45,1.6, height 0.95

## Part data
C1: library part 50527, "Polarized capacitor, pin 1 neg", Manufacturer=DNP
C2 C3 C4: library part 20116, "Ceramic chip capacitor", Manufacturer=Any, Package="2220 (5750 metric) chip capacitor", Part Number="10u, 100V, X5R, 2220 (5750 metric) chip capacitor", Voltage=100V
C5 C23 C25 C26 C27 C29 C31 C33 C34 C35 C36: library part 20027, "Ceramic chip capacitor", Manufacturer=Any, Package="0603 (1608 metric) chip capacitor", Part Number="100n, 50V, X5R, 0603 (1608 metric) chip capacitor", Voltage=50V
C6 C7 C8 C9: library part 20110, "Ceramic chip capacitor", Manufacturer=Any, Package="0603 (1608 metric) chip capacitor", Part Number="100n, 100V, X5R, 0603 (1608 metric) chip capacitor", Voltage=100V
C10: library part 20111, "Ceramic chip capacitor", Manufacturer=Any, Package="0603 (1608 metric) chip capacitor", Part Number="10u, 10V, X5R, 0603 (1608 metric) chip capacitor", Voltage=10V
C11: library part 20112, "Ceramic chip capacitor", Manufacturer=Any, Package="0603 (1608 metric) chip capacitor", Part Number="25p, 50V, C0G/NP0, 0603 (1608 metric) chip capacitor", Voltage=50V
C12: library part 20113, "Ceramic chip capacitor", Manufacturer=Any, Package="0603 (1608 metric) chip capacitor", Part Number="4.7u, 25V, X5R, 0603 (1608 metric) chip capacitor", Voltage=25V
C13 C14 C15 C16: library part 20077, "Ceramic chip capacitor", Manufacturer=Any, Package="0603 (1608 metric) chip capacitor", Part Number="1u, 25V, X5R, 0603 (1608 metric) chip capacitor", Voltage=25V
C17 C18 C19 C20: library part 30006, "Ceramic chip capacitor", Manufacturer=Murata, Package="1210 (3225 metric) chip capacitor", Part Number=GRM32ER71K475KE14L, Voltage=80V
C21 C22: library part 20083, "Ceramic chip capacitor", Manufacturer=Any, Package="0603 (1608 metric) chip capacitor", Part Number="100p, 100V, C0G/NP0, 0603 (1608 metric) chip capacitor", Voltage=100V
C24 C28 C30: library part 20056, "Ceramic chip capacitor", Manufacturer=Any, Package="0603 (1608 metric) chip capacitor", Part Number="2.2n, 50V, C0G/NP0, 0603 (1608 metric) chip capacitor", Voltage=50V
C32: library part 20084, "Ceramic chip capacitor", Manufacturer=Any, Package="0603 (1608 metric) chip capacitor", Part Number="4.7u, 10V, X5R, 0603 (1608 metric) chip capacitor", Voltage=10V
D1 D2 D3 D4 D5: library part 50491, "Schottky Diode, pin1 cathode", Manufacturer="Diotec  Semiconductor", Part Number=SKL110
D6 D7 D8 D9: library part 50513, "Zener, pin1 cathode", Manufacturer=Nexperia, Part Number=BZX384-B13
J1: library part 50289, "Trinamic 44-pin connector", Manufacturer=Samtec, Part Number=HLE-122-02-F-DV
J2: library part 50537, "1X2 pin connector", Manufacturer="Metz Connect", Part Number=AKL320-02
J3: library part 50511, "1X4 pin connector", Manufacturer="Metz Connect", Part Number=PT11304HBBN
J4: library part 50023, "1X2 pin connector", Manufacturer=Any, Part Number="1x2 2.54mm pin header"
L1: library part 60031, "Molded inductor", Current=740m, Manufacturer=Wuerth, Part Number=744031100, Tolerance=30
MP1 MP2 MP3 MP4: library part 50193, "Mounting hole", Part Number="M3 mounting hole"
Q1 Q2 Q3 Q4 Q5 Q6 Q7 Q8: library part 50489, "N-ch Enh-MOSFET; 5,6,7,8D 4G 1,2.3S", Manufacturer=Infineon, Part Number=BSC030N08NS5ATMA1
R1 R2 R3 R4 R8 R9 R13 R14 R18 R19 R31 R32: library part 10028, "Chip Resistor", Manufacturer=Any, Package="0603 (1608 metric) chip resistor", Part Number="10k, 1%, 100mW, 0603 (1608 metric) chip resistor", Power=100mW, Tolerance=1%
R5 R6 R7 R10 R11 R12 R15 R16 R17 R20 R21 R22: library part 10041, "Chip Resistor", Manufacturer=Any, Package="0603 (1608 metric) chip resistor", Part Number="2.2, 1%, 100mW, 0603 (1608 metric) chip resistor", Power=100mW, Tolerance=1%
R23: library part 10078, "Chip Resistor", Manufacturer=Any, Package="0603 (1608 metric) chip resistor", Part Number="12k, 1%, 100mW, 0603 (1608 metric) chip resistor", Power=100mW, Tolerance=1%
R24: library part 10152, "Chip Resistor", Manufacturer=Any, Package="0603 (1608 metric) chip resistor", Part Number="1.5k, 1%, 100mW, 0603 (1608 metric) chip resistor", Power=100mW, Tolerance=1%
R25 R26 R35 R36 R37 R38: library part 10157, "Chip Resistor", Manufacturer=Any, Package="2010 (5025 metric) chip resistor", Part Number="15m, 1%, 750mW, 2010 (5025 metric) chip resistor", Power=750mW, Tolerance=1%
R27 R28: library part 10016, "Chip Resistor", Manufacturer=Any, Package="0603 (1608 metric) chip resistor", Part Number="100, 1%, 100mW, 0603 (1608 metric) chip resistor", Power=100mW, Tolerance=1%
R29 R39 R40: library part 10049, "Chip Resistor", Manufacturer=Any, Package="0603 (1608 metric) chip resistor", Part Number="1k, 1%, 100mW, 0603 (1608 metric) chip resistor", Power=100mW, Tolerance=1%
R30: library part 40000, "Chip Resistor", Manufacturer=Epcos, Package="0603 (1608 metric) chip resistor", Part Number=B57330V2103J260, Power=180mW, Tolerance=5%
R33: library part 40007, "Chip Resistor", Manufacturer=DNP, Package="0603 (1608 metric) chip resistor"
R34: library part 10054, "Chip Resistor", Manufacturer=Any, Package="0603 (1608 metric) chip resistor", Part Number="0, -, -, 0603 (1608 metric) chip resistor", Power=-
R41: library part 10002, "Chip Resistor", Manufacturer=Any, Package="0603 (1608 metric) chip resistor", Part Number="10, 1%, 100mW, 0603 (1608 metric) chip resistor", Power=100mW, Tolerance=1%
TP1 TP2 TP3 TP4 TP5 TP6 TP7 TP8 TP9 TP10 TP11 TP_GND3: library part 50094, "Round testpoint"
TP_GND1 TP_GND2: library part 50149, "Round testpoint"
U1: library part 50499, "SPI Serial Flash Memory", Manufacturer=Atmel, Part Number=AT25128B-SSHL
U2 U3 U4 U5: library part 50490, "High Voltage 1A Peak Half Bridge Gate Driver", Manufacturer="Texas Instruments", Part Number=LM5109BSD/NOPB
U6: library part 50495, "LMR62014 SIMPLE SWITCHER® 20Vout, 1.4A Step-Up Voltage Regulator in SOT-23", Manufacturer="Texas Instruments", Part Number=LMR62014XMF/NOPB
U7 U8 U9: library part 50496, "Bidirectional, Zero Drift, Current Sense Amplifier", Manufacturer="Analog Devices", Part Number=AD8418ABRMZ
U10: library part 50426, "150-mA Low-noise LDO", Manufacturer="Texas Instruments", Part Number=LP2985-33DBV
U11: library part 50316, "Series voltage reference", Manufacturer="Texas Instruments", Part Number=REF3125

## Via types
v1: diameter 0.6, hole 0.25, Top Layer to Bottom Layer, tented both sides, 699 vias
v2: diameter 1, hole 0.6, Top Layer to Bottom Layer, tented both sides, 32 vias

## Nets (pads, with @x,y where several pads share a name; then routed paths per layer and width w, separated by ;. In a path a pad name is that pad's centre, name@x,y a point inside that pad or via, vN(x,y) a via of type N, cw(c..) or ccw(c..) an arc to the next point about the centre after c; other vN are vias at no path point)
+3V3: C5.2 C32.2 C33.2 C34.2 J4.1 R30.2 R33.1 TP10.1 U1.3 U1.7 U1.8 U10.5 U11.1 | length 136.3
  Top Layer w0.3: R30.2@32.25,28.2 32.4,28.2 33.35,27.25 v1(33.75,27.25) ; v1(53.825,11.345) U1.8@56.425,11.345 U1.7@56.425,12.615 57.715,12.615 58.985,13.885 U1.3@61.875,13.885 ; v1(61,27.15) C33.2@67.05,27.15 67.05,29.5 68.3,30.75 R33.1@68.3,33.3
  Top Layer w0.5: C33.2@67.05,27.15 C32.2@67.05,25.85 U10.5@67.05,24.425 68.275,23.2 69.8,23.2 70.65,22.35 C34.2@70.65,19.65 U11.1@70.65,18.1
  Mid2 w0.3: v1(53.825,11.345) 55.27,11.345 59.125,15.2 59.125,17.25 ; v1(61,27.15) 61,24.6 58.5,22.1 58.5,17.875 59.125,17.25 ; v1(81,13.5) 75.4,13.5 71.65,17.25 59.125,17.25
  Bottom Layer w0.3: v1(33.75,27.25) 34.4,27.9 53.3,27.9 54.05,27.15 v1(61,27.15) 61,42.25 51.25,52 J4.1@51.13,52
+5V: C10.2 C31.2 J1.42 L1.1 R34.1 TP2.1 U6.4 U6.5 U10.1 U10.3 | length 99.6
  Top Layer w0.3: v1(69.6,32.45) R34.1@69.6,33.3
  Top Layer w0.5: v1(17.5,9.2) v1(19.45,9.2) ; L1.1@57.075,24.7 57.85,24.7 58.175,24.375 U6.5@60.425,24.375 ; v1(59.575,25.75) C10.2@60.425,25.75 U6.5@60.425,24.375 ; v1(69.6,21.575) U10.3@68.95,21.575 68.95,21.928 68.378,22.5 67.575,22.5 67.05,21.975 U10.1@67.05,21.575 C31.2@67.05,20.15 66.275,20.15 62.325,24.1 U6.4@62.325,24.375 U6.5@60.425,24.375
  Mid2 w0.5: v1(17.5,9.2) v1(19.45,9.2) 26.525,9.2 28.7,11.375 51.225,11.375 54.975,15.125 56.275,15.125 57.25,16.1 57.25,23.425 v1(59.575,25.75)
  Bottom Layer w0.3: v1(69.6,32.45) v1(69.6,21.575) 76.425,21.575 TP2.1@81,17
+USH: C23.2 C27.1 C29.2 R33.2 R34.2 TP5.1 U7.6 U7.7 U8.6 U8.7 U9.6 U9.7 | length 48.7
  Top Layer w0.3: U8.7@57.425,45.025 U8.6@58.075,45.025 58.075,44.1 58.9,43.275 C27.1@60.25,43.275 ; U9.7@57.425,52.525 U9.6@58.075,52.525 58.075,51.8 59.025,50.85 C29.2@60.25,50.85 60.349,50.85 61.125,50.074 61.125,48.625 60.725,48.225 60.725,44.45 60.25,43.975 C27.1@60.25,43.275 ; U7.7@64.175,36.275 U7.6@64.825,36.275 64.825,35.475 65.7,34.6 C23.2@67,34.6 67.1,34.7 R33.2@68.3,34.7 ; v1(70.525,34.7) R34.2@69.6,34.7 R33.2@68.3,34.7 ; C27.1@60.25,43.275 61.65,43.275 67.5,37.425 67.5,35.75 68.3,34.95 R33.2@68.3,34.7
  Bottom Layer w0.3: v1(70.525,34.7) 77.3,34.7 TP5.1@81,31
+V_GD: C11.2 C12.2 C13.2 C14.2 C15.2 C16.2 D5.1 R5.1 R10.1 R15.1 R20.1 R23.2 TP3.1 U2.1 U3.1 U4.1 U5.1 | length 82.8
  Top Layer w0.4: R20.1@16.45,12.325 C16.2@17.55,12.325 ; C16.2@17.675,12.315 v1(18.625,12.315) U5.1@19.3,12.315 ; R15.1@25.95,12.325 C15.2@27.05,12.325 ; C15.2@27.175,12.315 v1(28.025,12.315) U4.1@28.8,12.315 ; R10.1@35.45,12.325 C14.2@36.55,12.325 ; C14.2@36.675,12.315 v1(37.55,12.315) U3.1@38.3,12.315 ; R5.1@44.975,12.325 C13.2@46.05,12.325 ; C13.2@46.175,12.315 v1(47.075,12.315) U2.1@47.8,12.315 ; v1(55.8,16.4) 58.275,18.875 v1(59.675,18.875) C12.2@59.675,17.55 R23.2@60.675,17.55 ; D5.1@58.575,19.35 59.025,18.9 C11.2@60.775,18.9
  Mid2 w0.4: v1(59.675,18.875) 64.8,24 v1(81.025,24)
  Bottom Layer w0.4: v1(18.625,12.315) v1(28.025,12.315) v1(37.55,12.315) v1(47.075,12.315) 49.975,12.315 52.76,15.1 54.5,15.1 v1(55.8,16.4)
C\S\_\C\H\1\: J1.7 U1.1 | length 10
  Top Layer w0.2: J1.7@61.65,2.8 61.65,2.95 60.4,4.2 60.4,10.45 61.295,11.345 U1.1@61.875,11.345
EXTREF_2V5: C36.2 J1.6 R41.2 TP11.1 | length 37.7
  Top Layer w0.3: J1.6@64.19,9.2 64.19,9.615 65.2,10.625 67.95,10.625 68.475,11.15 C36.2@70.65,11.15 R41.2@70.65,12.25 71.25,12.25 71.7,12.7 v1(72.3,12.7)
  Bottom Layer w0.3: v1(72.3,12.7) 79,12.7 79.8,11.9 82.05,11.9 83.4,13.25 83.4,25.1 TP11.1@81,27.5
